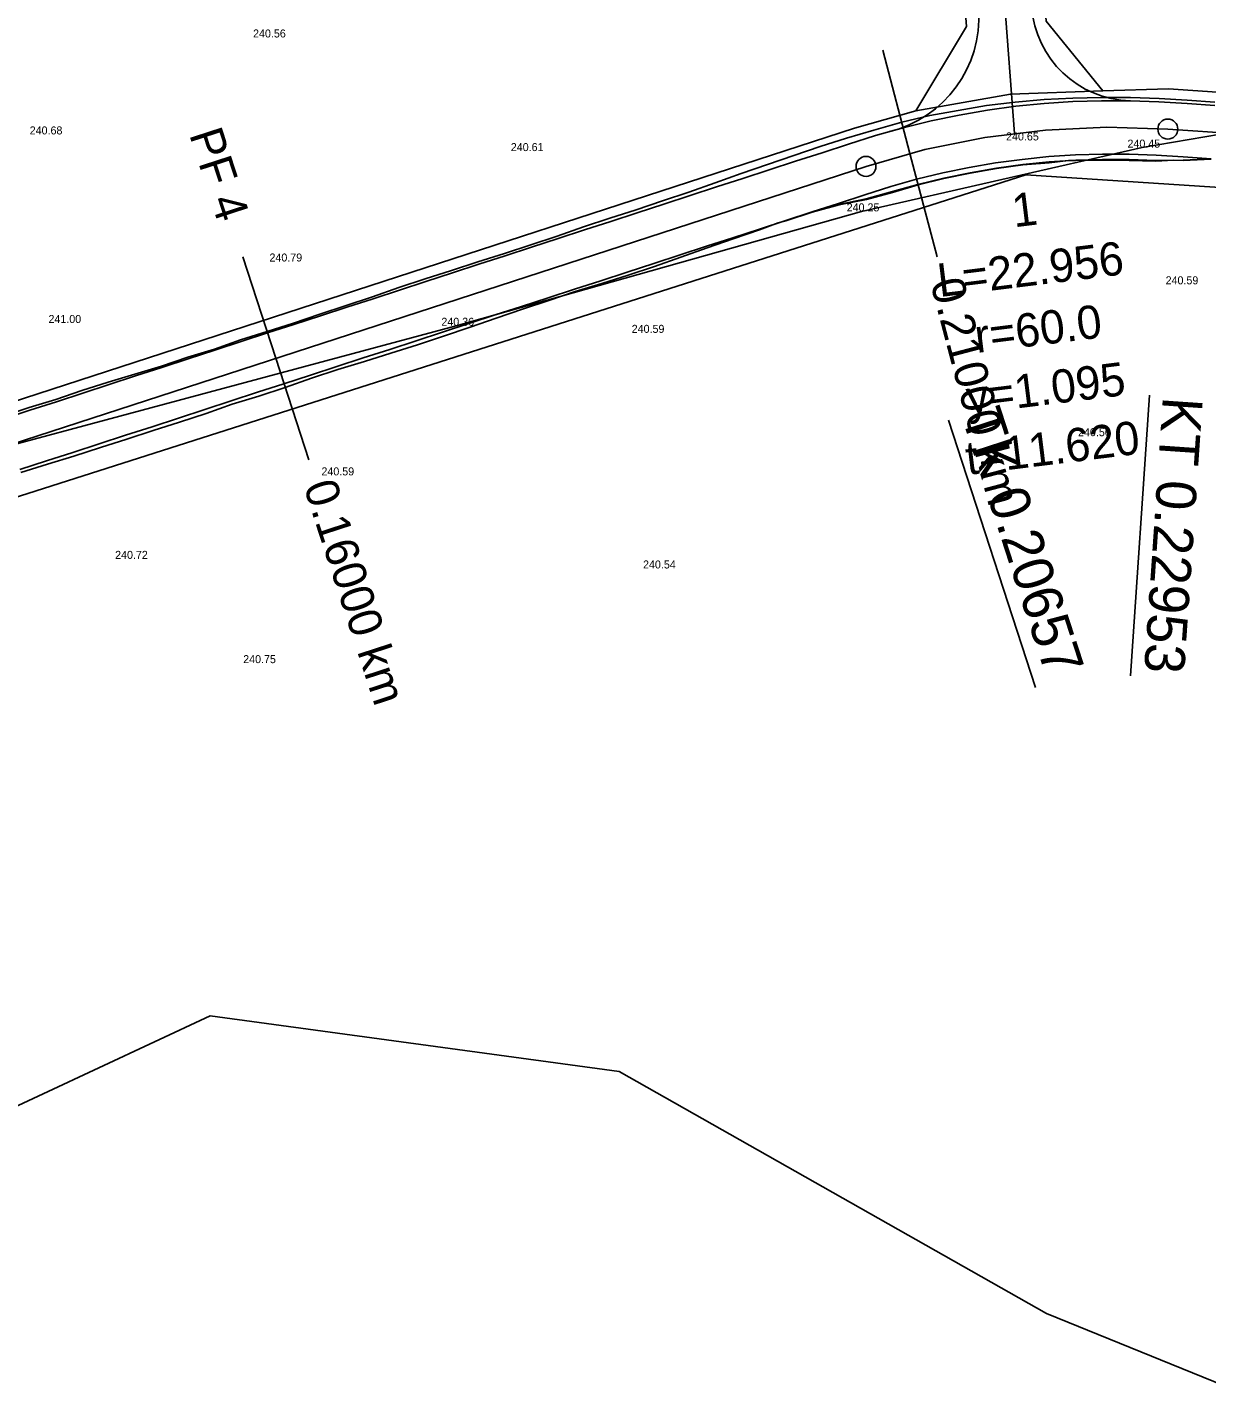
# Model space of a CAD drawing. Extents: x -555887 to -552101, y -1100251 to -1096546.
# Drawn here: x -554536.7 to -554448.2, y -1098460 to -1098358 of the extents above; entities that cross this region are included whole.
import ezdxf

# ---------------------------------------------------------------- set-up
doc = ezdxf.new("R2010")
doc.units = 0
for name, color, linetype in [('PARCELY_cesty', 7, 'Continuous'), ('POLYGONY_rozšíření', 7, 'Continuous'), ('POLYGONY_SITUACE_PF', 7, 'Continuous'), ('POLYGONY_SITUACE_PF_POPISY', 7, 'Continuous'), ('POLYGONY_SITUACE_PO', 7, 'Continuous'), ('vrstevnice', 7, 'Continuous'), ('Výškopis', 7, 'Continuous'), ('ZSST', 7, 'Continuous'), ('zájem', 7, 'Continuous')]:
    doc.layers.add(name, color=color, linetype=linetype)

msp = doc.modelspace()

# ---------------------------------------------------------------- linework, layer by layer
for p, q in [((-554452.47, -1098385.58), (-554453.91, -1098406.62)), ((-554467.56, -1098387.45), (-554461.04, -1098407.5))]:
    msp.add_line(p, q)
at = {"layer": 'PARCELY_cesty'}
for points in [[(-554455.97, -1098362.75), (-554460.23, -1098357.53), (-554490.64, -1097953.75), (-554489.26, -1097949.91)], [(-554470, -1098364.25), (-554466.22, -1098357.93), (-554496.57, -1097954.89), (-554499.05, -1097951.29)], [(-554666.58, -1098424.3), (-554661.61, -1098426.35), (-554474.62, -1098365.56), (-554470, -1098364.25), (-554462.92, -1098363), (-554455.97, -1098362.75), (-554451.05, -1098362.62), (-554296.95, -1098373.16), (-554290.89, -1098371.6), (-554270.39, -1098373.3), (-554264.04, -1098376.17), (-554253.34, -1098377.56), (-554081.03, -1098403.4), (-554065.66, -1098405.31), (-554039.82, -1098406.01), (-554011.2, -1098408.42), (-553994.13, -1098410.89)]]:
    msp.add_lwpolyline(points, dxfattribs=at)
at = {"layer": 'POLYGONY_rozšíření'}
for centre, radius, start, end in [((-554474.07, -1098357.29), 8.78, 283.6542, 4.0132), ((-554453.74, -1098355.91), 7.6, 184.3058, 268.6845)]:
    msp.add_arc(centre, radius, start, end, dxfattribs=at)
at = {"layer": 'POLYGONY_SITUACE_PF'}
for p, q in [((-554472.49, -1098359.72), (-554470.46, -1098367.46)), ((-554470.46, -1098367.46), (-554468.42, -1098375.2)), ((-554520.51, -1098375.22), (-554518.04, -1098382.82)), ((-554518.04, -1098382.82), (-554515.56, -1098390.43))]:
    msp.add_line(p, q, dxfattribs=at)
at = {"layer": 'POLYGONY_SITUACE_PO'}
for p, q in [((-554494.32, -1097944.76), (-554462.61, -1098365.96)), ((-554462.55, -1098363.61), (-554460.39, -1098363.42)), ((-554460.39, -1098363.42), (-554458.23, -1098363.31)), ((-554460.37, -1098363.71), (-554458.22, -1098363.56)), ((-554460.37, -1098363.71), (-554458.22, -1098363.56)), ((-554458.23, -1098363.31), (-554456.07, -1098363.25)), ((-554458.22, -1098363.56), (-554456.07, -1098363.5)), ((-554458.22, -1098363.56), (-554456.07, -1098363.5)), ((-554456.07, -1098363.25), (-554453.91, -1098363.25)), ((-554456.07, -1098363.5), (-554453.92, -1098363.5)), ((-554456.07, -1098363.5), (-554453.92, -1098363.5)), ((-554453.92, -1098363.5), (-554451.77, -1098363.59)), ((-554453.92, -1098363.5), (-554451.77, -1098363.59)), ((-554453.91, -1098363.25), (-554451.75, -1098363.34)), ((-554451.75, -1098363.34), (-554449.64, -1098363.45)), ((-554449.64, -1098363.45), (-554447.57, -1098363.61)), ((-554468.96, -1098364.62), (-554466.83, -1098364.24)), ((-554468.87, -1098365.01), (-554466.77, -1098364.58)), ((-554468.87, -1098365.01), (-554466.77, -1098364.58)), ((-554466.83, -1098364.24), (-554464.7, -1098363.87)), ((-554466.77, -1098364.58), (-554464.64, -1098364.21)), ((-554466.77, -1098364.58), (-554464.64, -1098364.21)), ((-554464.7, -1098363.87), (-554462.55, -1098363.61)), ((-554464.64, -1098364.21), (-554462.51, -1098363.92)), ((-554464.64, -1098364.21), (-554462.51, -1098363.92)), ((-554462.51, -1098363.92), (-554460.37, -1098363.71)), ((-554462.51, -1098363.92), (-554460.37, -1098363.71)), ((-554451.77, -1098363.59), (-554449.66, -1098363.72)), ((-554451.77, -1098363.59), (-554449.66, -1098363.72)), ((-554449.66, -1098363.72), (-554447.58, -1098363.86)), ((-554449.66, -1098363.72), (-554447.58, -1098363.86)), ((-554473.16, -1098365.7), (-554471.07, -1098365.11)), ((-554473.04, -1098366.11), (-554470.97, -1098365.53)), ((-554473.04, -1098366.11), (-554470.97, -1098365.53)), ((-554471.07, -1098365.11), (-554468.96, -1098364.62)), ((-554470.97, -1098365.53), (-554468.87, -1098365.01)), ((-554470.97, -1098365.53), (-554468.87, -1098365.01)), ((-554460.28, -1098365.7), (-554455.69, -1098365.49)), ((-554455.69, -1098365.49), (-554451.1, -1098365.63)), ((-554477.19, -1098366.94), (-554475.21, -1098366.31)), ((-554475.21, -1098366.31), (-554473.16, -1098365.7)), ((-554475.07, -1098366.75), (-554473.04, -1098366.11)), ((-554475.07, -1098366.75), (-554473.04, -1098366.11)), ((-554469.33, -1098367.17), (-554464.83, -1098366.26)), ((-554464.83, -1098366.26), (-554460.28, -1098365.7)), ((-554451.1, -1098365.63), (-554287.2, -1098376.83)), ((-554481.14, -1098368.28), (-554479.17, -1098367.61)), ((-554479.17, -1098367.61), (-554477.19, -1098366.94)), ((-554479.03, -1098368.04), (-554477.05, -1098367.4)), ((-554479.03, -1098368.04), (-554477.05, -1098367.4)), ((-554477.05, -1098367.4), (-554475.07, -1098366.75)), ((-554477.05, -1098367.4), (-554475.07, -1098366.75)), ((-554473.75, -1098368.43), (-554469.33, -1098367.17)), ((-554460.04, -1098367.69), (-554458.03, -1098367.56)), ((-554458.03, -1098367.56), (-554456.01, -1098367.5)), ((-554456.01, -1098367.5), (-554454, -1098367.5)), ((-554454, -1098367.5), (-554451.99, -1098367.58)), ((-554451.99, -1098367.58), (-554449.94, -1098367.71)), ((-554670.2, -1098432.29), (-554473.75, -1098368.43)), ((-554483.11, -1098368.96), (-554481.14, -1098368.28)), ((-554481.01, -1098368.68), (-554479.03, -1098368.04)), ((-554481.01, -1098368.68), (-554479.03, -1098368.04)), ((-554467.99, -1098368.92), (-554466.02, -1098368.51)), ((-554466.02, -1098368.51), (-554464.03, -1098368.17)), ((-554465.94, -1098368.9), (-554463.97, -1098368.56)), ((-554465.94, -1098368.93), (-554463.97, -1098368.58)), ((-554464.03, -1098368.17), (-554462.04, -1098367.9)), ((-554463.97, -1098368.56), (-554461.99, -1098368.29)), ((-554463.97, -1098368.58), (-554461.99, -1098368.32)), ((-554462.04, -1098367.9), (-554460.04, -1098367.69)), ((-554461.99, -1098368.29), (-554460, -1098368.09)), ((-554461.99, -1098368.32), (-554460, -1098368.15)), ((-554460, -1098368.09), (-554458.01, -1098367.96)), ((-554460, -1098368.15), (-554458.55, -1098367.99)), ((-554458.55, -1098367.99), (-554458.01, -1098367.98)), ((-554458.01, -1098367.96), (-554456.01, -1098367.9)), ((-554458.01, -1098367.98), (-554456.01, -1098367.95)), ((-554456.01, -1098367.9), (-554454.01, -1098367.9)), ((-554456.01, -1098367.95), (-554454.01, -1098367.98)), ((-554454.01, -1098367.9), (-554452.01, -1098367.98)), ((-554454.01, -1098367.98), (-554452.01, -1098368.04)), ((-554452.01, -1098367.98), (-554449.95, -1098367.95)), ((-554452.01, -1098368.04), (-554450.67, -1098367.96)), ((-554450.67, -1098367.96), (-554449.95, -1098367.99)), ((-554449.95, -1098367.95), (-554447.86, -1098367.85)), ((-554449.95, -1098367.99), (-554447.86, -1098367.89)), ((-554449.94, -1098367.71), (-554447.86, -1098367.85)), ((-554487.04, -1098370.35), (-554485.08, -1098369.65)), ((-554485.08, -1098369.65), (-554483.11, -1098368.96)), ((-554484.97, -1098369.97), (-554482.99, -1098369.33)), ((-554484.97, -1098369.97), (-554482.99, -1098369.33)), ((-554482.99, -1098369.33), (-554481.01, -1098368.68)), ((-554482.99, -1098369.33), (-554481.01, -1098368.68)), ((-554471.89, -1098369.94), (-554469.95, -1098369.39)), ((-554469.95, -1098369.39), (-554467.99, -1098368.92)), ((-554469.85, -1098369.78), (-554467.9, -1098369.31)), ((-554469.84, -1098369.81), (-554467.9, -1098369.33)), ((-554467.9, -1098369.31), (-554465.94, -1098368.9)), ((-554467.9, -1098369.33), (-554465.94, -1098368.93)), ((-554489.02, -1098371), (-554487.04, -1098370.35)), ((-554488.93, -1098371.26), (-554486.95, -1098370.62)), ((-554488.93, -1098371.26), (-554486.95, -1098370.62)), ((-554486.95, -1098370.62), (-554484.97, -1098369.97)), ((-554486.95, -1098370.62), (-554484.97, -1098369.97)), ((-554475.81, -1098371.2), (-554473.83, -1098370.56)), ((-554473.83, -1098370.56), (-554471.89, -1098369.94)), ((-554473.73, -1098370.86), (-554471.77, -1098370.32)), ((-554473.72, -1098370.91), (-554471.75, -1098370.39)), ((-554471.77, -1098370.32), (-554469.85, -1098369.78)), ((-554471.75, -1098370.39), (-554469.84, -1098369.81)), ((-554492.97, -1098372.32), (-554490.99, -1098371.68)), ((-554490.99, -1098371.68), (-554489.02, -1098371)), ((-554490.92, -1098371.91), (-554488.93, -1098371.26)), ((-554490.92, -1098371.91), (-554488.93, -1098371.26)), ((-554477.79, -1098371.84), (-554475.81, -1098371.2)), ((-554477.79, -1098371.84), (-554475.78, -1098371.29)), ((-554477.79, -1098371.86), (-554475.77, -1098371.32)), ((-554475.78, -1098371.29), (-554473.73, -1098370.86)), ((-554475.77, -1098371.32), (-554473.72, -1098370.91)), ((-554494.95, -1098372.97), (-554492.97, -1098372.32)), ((-554494.88, -1098373.19), (-554492.9, -1098372.55)), ((-554494.88, -1098373.19), (-554492.9, -1098372.55)), ((-554492.9, -1098372.55), (-554490.92, -1098371.91)), ((-554492.9, -1098372.55), (-554490.92, -1098371.91)), ((-554481.75, -1098373.13), (-554479.77, -1098372.49)), ((-554481.75, -1098373.13), (-554479.77, -1098372.49)), ((-554481.74, -1098373.19), (-554480.33, -1098372.67)), ((-554480.33, -1098372.67), (-554479.77, -1098372.51)), ((-554479.77, -1098372.49), (-554477.79, -1098371.84)), ((-554479.77, -1098372.49), (-554477.79, -1098371.84)), ((-554479.77, -1098372.51), (-554477.79, -1098371.86)), ((-554498.9, -1098374.31), (-554496.92, -1098373.65)), ((-554496.92, -1098373.65), (-554494.95, -1098372.97)), ((-554496.86, -1098373.84), (-554494.88, -1098373.19)), ((-554496.86, -1098373.84), (-554494.88, -1098373.19)), ((-554483.74, -1098373.78), (-554481.75, -1098373.13)), ((-554483.74, -1098373.78), (-554481.75, -1098373.13)), ((-554483.71, -1098373.87), (-554481.74, -1098373.19)), ((-554500.88, -1098374.96), (-554498.9, -1098374.31)), ((-554500.82, -1098375.13), (-554498.84, -1098374.48)), ((-554500.82, -1098375.13), (-554498.84, -1098374.48)), ((-554498.84, -1098374.48), (-554496.86, -1098373.84)), ((-554498.84, -1098374.48), (-554496.86, -1098373.84)), ((-554487.7, -1098375.06), (-554485.72, -1098374.42)), ((-554487.7, -1098375.06), (-554485.72, -1098374.42)), ((-554487.64, -1098375.24), (-554485.68, -1098374.54)), ((-554485.72, -1098374.42), (-554483.74, -1098373.78)), ((-554485.72, -1098374.42), (-554483.74, -1098373.78)), ((-554485.68, -1098374.54), (-554483.71, -1098373.87)), ((-554504.84, -1098376.23), (-554502.87, -1098375.58)), ((-554504.78, -1098376.41), (-554502.8, -1098375.77)), ((-554504.78, -1098376.41), (-554502.8, -1098375.77)), ((-554502.87, -1098375.58), (-554500.88, -1098374.96)), ((-554502.8, -1098375.77), (-554500.82, -1098375.13)), ((-554502.8, -1098375.77), (-554500.82, -1098375.13)), ((-554491.66, -1098376.35), (-554489.68, -1098375.71)), ((-554491.66, -1098376.35), (-554489.68, -1098375.71)), ((-554489.68, -1098375.71), (-554487.7, -1098375.06)), ((-554489.68, -1098375.71), (-554487.7, -1098375.06)), ((-554489.61, -1098375.93), (-554487.64, -1098375.24)), ((-554506.83, -1098376.87), (-554504.84, -1098376.23)), ((-554506.77, -1098377.06), (-554504.78, -1098376.41)), ((-554506.77, -1098377.06), (-554504.78, -1098376.41)), ((-554493.64, -1098377), (-554491.66, -1098376.35)), ((-554493.64, -1098377), (-554491.66, -1098376.35)), ((-554493.57, -1098377.21), (-554491.59, -1098376.58)), ((-554491.59, -1098376.58), (-554489.61, -1098375.93)), ((-554510.77, -1098378.21), (-554508.81, -1098377.51)), ((-554510.73, -1098378.35), (-554508.75, -1098377.7)), ((-554510.73, -1098378.35), (-554508.75, -1098377.7)), ((-554508.81, -1098377.51), (-554506.83, -1098376.87)), ((-554508.75, -1098377.7), (-554506.77, -1098377.06)), ((-554508.75, -1098377.7), (-554506.77, -1098377.06)), ((-554497.6, -1098378.29), (-554495.62, -1098377.64)), ((-554497.6, -1098378.29), (-554495.62, -1098377.64)), ((-554497.54, -1098378.48), (-554495.57, -1098377.81)), ((-554495.62, -1098377.64), (-554493.64, -1098377)), ((-554495.62, -1098377.64), (-554493.64, -1098377)), ((-554495.57, -1098377.81), (-554493.57, -1098377.21)), ((-554514.73, -1098379.52), (-554512.75, -1098378.87)), ((-554512.75, -1098378.87), (-554510.77, -1098378.21)), ((-554512.71, -1098378.99), (-554510.73, -1098378.35)), ((-554512.71, -1098378.99), (-554510.73, -1098378.35)), ((-554499.59, -1098378.93), (-554497.6, -1098378.29)), ((-554499.59, -1098378.93), (-554497.6, -1098378.29)), ((-554499.52, -1098379.14), (-554497.54, -1098378.48)), ((-554516.7, -1098380.18), (-554514.73, -1098379.52)), ((-554516.67, -1098380.28), (-554514.69, -1098379.63)), ((-554516.67, -1098380.28), (-554514.69, -1098379.63)), ((-554514.69, -1098379.63), (-554512.71, -1098378.99)), ((-554514.69, -1098379.63), (-554512.71, -1098378.99)), ((-554503.55, -1098380.22), (-554501.57, -1098379.57)), ((-554503.55, -1098380.22), (-554501.57, -1098379.57)), ((-554503.46, -1098380.49), (-554501.49, -1098379.8)), ((-554501.57, -1098379.57), (-554499.59, -1098378.93)), ((-554501.57, -1098379.57), (-554499.59, -1098378.93)), ((-554501.49, -1098379.8), (-554499.52, -1098379.14)), ((-554520.68, -1098381.44), (-554518.69, -1098380.82)), ((-554518.69, -1098380.82), (-554516.7, -1098380.18)), ((-554518.65, -1098380.92), (-554516.67, -1098380.28)), ((-554518.65, -1098380.92), (-554516.67, -1098380.28)), ((-554507.51, -1098381.51), (-554505.53, -1098380.86)), ((-554507.51, -1098381.51), (-554505.53, -1098380.86)), ((-554505.53, -1098380.86), (-554503.55, -1098380.22)), ((-554505.53, -1098380.86), (-554503.55, -1098380.22)), ((-554505.44, -1098381.15), (-554503.46, -1098380.49)), ((-554522.64, -1098382.13), (-554520.68, -1098381.44)), ((-554522.62, -1098382.21), (-554520.63, -1098381.57)), ((-554522.62, -1098382.21), (-554520.63, -1098381.57)), ((-554520.63, -1098381.57), (-554518.65, -1098380.92)), ((-554520.63, -1098381.57), (-554518.65, -1098380.92)), ((-554509.49, -1098382.15), (-554507.51, -1098381.51)), ((-554509.49, -1098382.15), (-554507.51, -1098381.51)), ((-554509.4, -1098382.43), (-554507.41, -1098381.8)), ((-554507.41, -1098381.8), (-554505.44, -1098381.15)), ((-554526.61, -1098383.4), (-554524.64, -1098382.73)), ((-554526.58, -1098383.5), (-554524.6, -1098382.86)), ((-554526.58, -1098383.5), (-554524.6, -1098382.86)), ((-554524.64, -1098382.73), (-554522.64, -1098382.13)), ((-554524.6, -1098382.86), (-554522.62, -1098382.21)), ((-554524.6, -1098382.86), (-554522.62, -1098382.21)), ((-554513.45, -1098383.44), (-554511.47, -1098382.79)), ((-554513.45, -1098383.44), (-554511.47, -1098382.79)), ((-554511.47, -1098382.79), (-554509.49, -1098382.15)), ((-554511.47, -1098382.79), (-554509.49, -1098382.15)), ((-554511.39, -1098383.05), (-554509.4, -1098382.43)), ((-554528.6, -1098384.02), (-554526.61, -1098383.4)), ((-554528.56, -1098384.14), (-554526.58, -1098383.5)), ((-554528.56, -1098384.14), (-554526.58, -1098383.5)), ((-554515.44, -1098384.08), (-554513.45, -1098383.44)), ((-554515.44, -1098384.08), (-554513.45, -1098383.44)), ((-554515.36, -1098384.32), (-554513.38, -1098383.66)), ((-554513.38, -1098383.66), (-554511.39, -1098383.05)), ((-554532.58, -1098385.24), (-554530.6, -1098384.6)), ((-554532.52, -1098385.43), (-554530.54, -1098384.79)), ((-554532.52, -1098385.43), (-554530.54, -1098384.79)), ((-554530.6, -1098384.6), (-554528.6, -1098384.02)), ((-554530.54, -1098384.79), (-554528.56, -1098384.14)), ((-554530.54, -1098384.79), (-554528.56, -1098384.14)), ((-554519.4, -1098385.37), (-554517.42, -1098384.73)), ((-554519.4, -1098385.37), (-554517.42, -1098384.73)), ((-554517.42, -1098384.73), (-554515.44, -1098384.08)), ((-554517.42, -1098384.73), (-554515.44, -1098384.08)), ((-554517.33, -1098385), (-554515.36, -1098384.32)), ((-554536.55, -1098386.51), (-554534.55, -1098385.92)), ((-554534.55, -1098385.92), (-554532.58, -1098385.24)), ((-554534.5, -1098386.08), (-554532.52, -1098385.43)), ((-554534.5, -1098386.08), (-554532.52, -1098385.43)), ((-554521.38, -1098386.02), (-554519.4, -1098385.37)), ((-554521.38, -1098386.02), (-554519.4, -1098385.37)), ((-554521.3, -1098386.26), (-554519.31, -1098385.66)), ((-554519.31, -1098385.66), (-554517.33, -1098385)), ((-554538.53, -1098387.18), (-554536.55, -1098386.51)), ((-554538.47, -1098387.36), (-554536.48, -1098386.72)), ((-554538.47, -1098387.36), (-554536.48, -1098386.72)), ((-554536.48, -1098386.72), (-554534.5, -1098386.08)), ((-554536.48, -1098386.72), (-554534.5, -1098386.08)), ((-554525.34, -1098387.3), (-554523.36, -1098386.66)), ((-554525.34, -1098387.3), (-554523.36, -1098386.66)), ((-554525.25, -1098387.6), (-554523.27, -1098386.95)), ((-554523.36, -1098386.66), (-554521.38, -1098386.02)), ((-554523.36, -1098386.66), (-554521.38, -1098386.02)), ((-554523.27, -1098386.95), (-554521.3, -1098386.26)), ((-554529.3, -1098388.59), (-554527.32, -1098387.95)), ((-554529.3, -1098388.59), (-554527.32, -1098387.95)), ((-554527.32, -1098387.95), (-554525.34, -1098387.3)), ((-554527.32, -1098387.95), (-554525.34, -1098387.3)), ((-554527.23, -1098388.23), (-554525.25, -1098387.6)), ((-554531.29, -1098389.24), (-554529.3, -1098388.59)), ((-554531.29, -1098389.24), (-554529.3, -1098388.59)), ((-554531.19, -1098389.52), (-554529.21, -1098388.89)), ((-554529.21, -1098388.89), (-554527.23, -1098388.23)), ((-554535.25, -1098390.52), (-554533.27, -1098389.88)), ((-554535.25, -1098390.52), (-554533.27, -1098389.88)), ((-554533.27, -1098389.88), (-554531.29, -1098389.24)), ((-554533.27, -1098389.88), (-554531.29, -1098389.24)), ((-554533.18, -1098390.15), (-554531.19, -1098389.52)), ((-554537.23, -1098391.17), (-554535.25, -1098390.52)), ((-554537.23, -1098391.17), (-554535.25, -1098390.52)), ((-554537.16, -1098391.39), (-554535.17, -1098390.76)), ((-554535.17, -1098390.76), (-554533.18, -1098390.15))]:
    msp.add_line(p, q, dxfattribs=at)
for centre in [(-554451.1, -1098365.63), (-554473.75, -1098368.43)]:
    msp.add_circle(centre, 0.75, dxfattribs=at)
at = {"layer": 'vrstevnice'}
for points in [[(-554628.43, -1098605.83), (-554624.78, -1098606.25), (-554624.21, -1098605.68), (-554622.95, -1098605.83), (-554605.82, -1098599.51), (-554598.25, -1098561.84), (-554578.44, -1098501.17), (-554563.39, -1098471.18), (-554543.87, -1098441.89), (-554522.95, -1098432.12)], [(-554522.95, -1098432.12), (-554492.28, -1098436.31), (-554460.21, -1098454.44), (-554415.59, -1098472.57), (-554357.03, -1098493.49), (-554288.71, -1098499.07), (-554230.77, -1098502.48)]]:
    msp.add_lwpolyline(points, dxfattribs=at)
at = {"layer": 'ZSST'}
msp.add_lwpolyline([(-554664.51, -1098427.29), (-554593.24, -1098405.5), (-554564.12, -1098396.39), (-554504.51, -1098380.38), (-554474.09, -1098371.8), (-554453.04, -1098367.02), (-554440.1, -1098364.81), (-554432.74, -1098364.37), (-554410.92, -1098364.7), (-554369.44, -1098366), (-554333.38, -1098368), (-554270.17, -1098373.82), (-554215.58, -1098380.33), (-554205.6, -1098382.24), (-554194.57, -1098383.81), (-554169.13, -1098388.36), (-554184.13, -1098381.1), (-554194.68, -1098382.34), (-554205.5, -1098381.25), (-554215.58, -1098380.33)], dxfattribs=at)
at = {"layer": 'zájem'}
for points in [[(-555057.79, -1098455.7), (-554947.91, -1098379.76), (-554868.79, -1098324.5), (-554807.83, -1098282.81), (-554734.83, -1098232.28), (-554733.03, -1098237.3), (-554723.03, -1098264.9), (-554699.69, -1098346.16), (-554674.86, -1098437.73), (-554672.03, -1098436.78), (-554666.38, -1098434.92), (-554663.87, -1098434.13), (-554584.1, -1098408.07), (-554542.63, -1098394.85), (-554461.77, -1098369.06), (-554380.5, -1098374.37), (-554285.56, -1098379.8), (-554280.9, -1098380.23), (-554271.92, -1098380.9), (-554131.79, -1098402.65)], [(-554131.79, -1098402.65), (-554271.92, -1098380.9), (-554280.9, -1098380.23), (-554285.56, -1098379.8), (-554380.5, -1098374.37), (-554461.77, -1098369.06), (-554542.63, -1098394.85), (-554584.1, -1098408.07), (-554663.87, -1098434.13), (-554666.38, -1098434.92), (-554672.03, -1098436.78), (-554674.86, -1098437.73), (-554699.69, -1098346.16), (-554723.03, -1098264.9), (-554733.03, -1098237.3), (-554734.83, -1098232.28), (-554807.83, -1098282.81), (-554868.79, -1098324.5), (-554947.91, -1098379.76), (-555057.79, -1098455.7)]]:
    msp.add_lwpolyline(points, dxfattribs=at)

# ---------------------------------------------------------------- texts
for s, height, rotation, p in [('1', 2.5, 7.0494, (-554462.63, -1098373)), ('L=22.956', 2.5, 7.0494, (-554468.23, -1098378.23)), ('r=60.0', 2.5, 7.0494, (-554465.44, -1098382.42)), ('y=1.095', 2.5, 7.0494, (-554466.07, -1098387.03)), ('KT 0.22953', 3, 266.0887, (-554451.47, -1098385.65)), ('TK 0.20657', 3, 288.0101, (-554466.61, -1098387.14)), ('t=11.620', 2.5, 7.0494, (-554466.11, -1098391.57))]:
    msp.add_text(s, height=height, rotation=rotation).set_placement(p)
at = {"layer": 'POLYGONY_SITUACE_PF_POPISY'}
for s, rotation, p in [('PF 4', 288.0101, (-554524.55, -1098366.02)), ('0.21000 km', 284.7353, (-554468.94, -1098377.15)), ('0.16000 km', 288.0101, (-554515.97, -1098392.41))]:
    msp.add_text(s, height=2.5, rotation=rotation, dxfattribs=at).set_placement(p)
at = {"layer": 'Výškopis'}
for s, p in [('240.56', (-554519.74, -1098358.76)), ('240.68', (-554536.5, -1098366.03)), ('240.65', (-554463.24, -1098366.48)), ('240.45', (-554454.13, -1098367.02)), ('240.61', (-554500.4, -1098367.28)), ('240.25', (-554475.2, -1098371.8)), ('240.79', (-554518.51, -1098375.56)), ('240.59', (-554451.27, -1098377.27)), ('241.00', (-554535.09, -1098380.17)), ('240.36', (-554505.61, -1098380.38)), ('240.59', (-554491.33, -1098380.91)), ('240.56', (-554457.84, -1098388.66)), ('240.59', (-554514.61, -1098391.6)), ('240.72', (-554530.09, -1098397.86)), ('240.54', (-554490.48, -1098398.58)), ('240.75', (-554520.48, -1098405.68))]:
    msp.add_text(s, height=0.6, dxfattribs=at).set_placement(p)

doc.saveas('drawing.dxf')
